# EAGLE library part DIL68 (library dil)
SOCKET Dual In Line
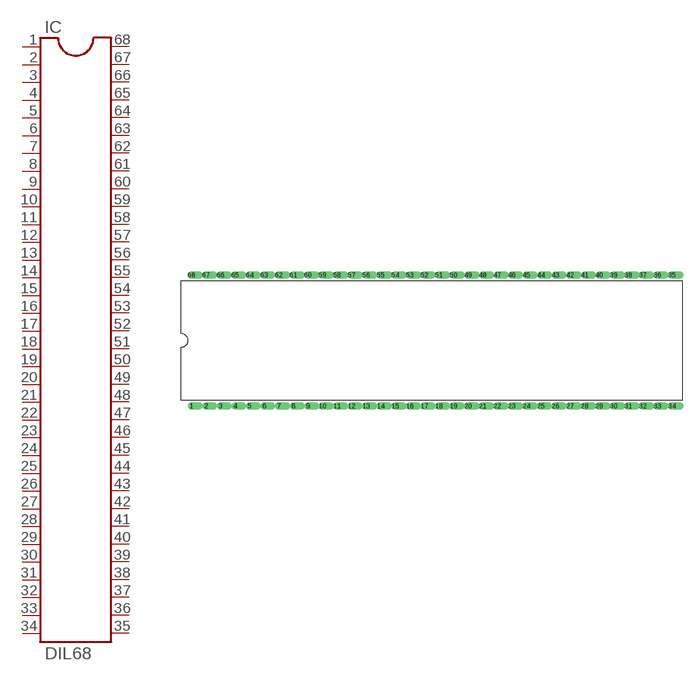
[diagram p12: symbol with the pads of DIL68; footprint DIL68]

Designator prefix IC

## DIL68  [DIL68]
1  1  pas
2  2  pas
3  3  pas
4  4  pas
5  5  pas
6  6  pas
7  7  pas
8  8  pas
9  9  pas
10  10  pas
11  11  pas
12  12  pas
13  13  pas
14  14  pas
15  15  pas
16  16  pas
17  17  pas
18  18  pas
19  19  pas
20  20  pas
21  21  pas
22  22  pas
23  23  pas
24  24  pas
25  25  pas
26  26  pas
27  27  pas
28  28  pas
29  29  pas
30  30  pas
31  31  pas
32  32  pas
33  33  pas
34  34  pas
35  35  pas
36  36  pas
37  37  pas
38  38  pas
39  39  pas
40  40  pas
41  41  pas
42  42  pas
43  43  pas
44  44  pas
45  45  pas
46  46  pas
47  47  pas
48  48  pas
49  49  pas
50  50  pas
51  51  pas
52  52  pas
53  53  pas
54  54  pas
55  55  pas
56  56  pas
57  57  pas
58  58  pas
59  59  pas
60  60  pas
61  61  pas
62  62  pas
63  63  pas
64  64  pas
65  65  pas
66  66  pas
67  67  pas
68  68  pas

## Footprint DIL68 (pad centres in mm)
SOCKET Dual In Line
drill 0.813 offset: 1 -41.91,-11.43; 2 -39.37,-11.43; 3 -36.83,-11.43; 4 -34.29,-11.43; 5 -31.75,-11.43; 6 -29.21,-11.43; 7 -26.67,-11.43; 8 -24.13,-11.43; 9 -21.59,-11.43; 10 -19.05,-11.43; 11 -16.51,-11.43; 12 -13.97,-11.43; 13 -11.43,-11.43; 14 -8.89,-11.43; 15 -6.35,-11.43; 16 -3.81,-11.43; 17 -1.27,-11.43; 18 1.27,-11.43; 19 3.81,-11.43; 20 6.35,-11.43; 21 8.89,-11.43; 22 11.43,-11.43; 23 13.97,-11.43; 24 16.51,-11.43; 25 19.05,-11.43; 26 21.59,-11.43; 27 24.13,-11.43; 28 26.67,-11.43; 29 29.21,-11.43; 30 31.75,-11.43; 31 34.29,-11.43; 32 36.83,-11.43; 33 39.37,-11.43; 34 41.91,-11.43; 35 41.91,11.43; 36 39.37,11.43; 37 36.83,11.43; 38 34.29,11.43; 39 31.75,11.43; 40 29.21,11.43; 41 26.67,11.43; 42 24.13,11.43; 43 21.59,11.43; 44 19.05,11.43; 45 16.51,11.43; 46 13.97,11.43; 47 11.43,11.43; 48 8.89,11.43; 49 6.35,11.43; 50 3.81,11.43; 51 1.27,11.43; 52 -1.27,11.43; 53 -3.81,11.43; 54 -6.35,11.43; 55 -8.89,11.43; 56 -11.43,11.43; 57 -13.97,11.43; 58 -16.51,11.43; 59 -19.05,11.43; 60 -21.59,11.43; 61 -24.13,11.43; 62 -26.67,11.43; 63 -29.21,11.43; 64 -31.75,11.43; 65 -34.29,11.43; 66 -36.83,11.43; 67 -39.37,11.43; 68 -41.91,11.43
